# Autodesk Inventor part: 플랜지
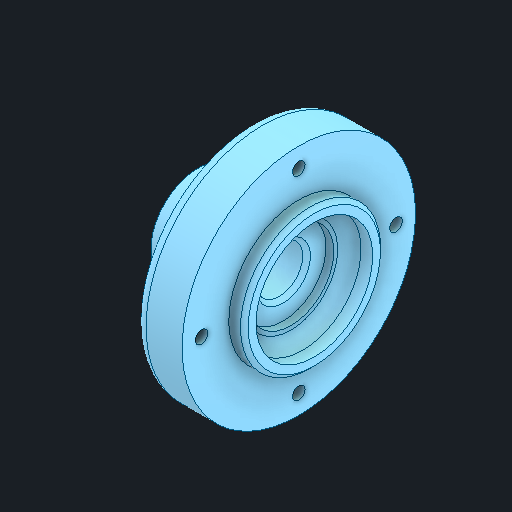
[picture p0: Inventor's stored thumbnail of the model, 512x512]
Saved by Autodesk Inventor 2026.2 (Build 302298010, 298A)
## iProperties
Created: 2026-03
Part Number: 플랜지
Material: 강철, 연강
Document SubType Name: Modeling
Designer: PC2-02
Density: 7.85 g/cm^3
Appearance: 기본값
Author: jhkim
Sending System: Autodesk Inventor 2026
Preprocessor: ST-DEVELOPER v20.1
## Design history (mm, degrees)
feature "솔리드1"
node "솔리드2"
